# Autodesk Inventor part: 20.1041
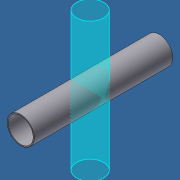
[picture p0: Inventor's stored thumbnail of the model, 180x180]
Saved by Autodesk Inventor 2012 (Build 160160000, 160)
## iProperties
Created: 2007-07
Part Number: 20.1041
Material: Aluminum-6061
Document SubType Name: Modeling
Designer: Andy Moles
Mass: 209.233 g
Surface Area: 778.11 cm^2
Volume: 77.2078 cm^3
Density: 2.71 g/cm^3
Description: Tube AL 50 X 2 L = SPECIFY
Vendor: F
Author: Andy Moles
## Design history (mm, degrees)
sketch "Sketch1"
  geometry: C1 r 23 at (0, 0); C2 r 25 at (0, 0); 1 further point
  constraints: 2 centre point, 2 coincident
  dimensions: "d0" = 46 diameter of C1; "d1" = 50 diameter of C2
extrude "Extrusion1" new body sketch "Sketch1" stored distance "d2" = 256 (= AL_TUBE); taper "d3" = 0 deg
body "Solid1"
other parameters: "AL_TUBE" = 256 (computed from FRAME_ID) [user parameter; used in 1 equation term]
